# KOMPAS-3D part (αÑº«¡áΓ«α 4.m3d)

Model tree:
1. Эскиз:1
2. Операция выдавливания:36
     Толщина стенки 1 = 2; Толщина стенки 2 = 6; Расстояние 1 = 1; Расстояние 2 = 3
3. Эскиз:38
4. Операция выдавливания:40
     Толщина стенки 1 = 2; Толщина стенки 2 = 6; Расстояние 1 = 5; Расстояние 2 = 3
5. Эскиз:39
6. Операция выдавливания:41
     Толщина стенки 1 = 2; Толщина стенки 2 = 6; Расстояние 1 = 1; Расстояние 2 = 3
7. Эскиз:40
8. Операция выдавливания:42
     Толщина стенки 1 = 2; Толщина стенки 2 = 2.5; Расстояние 1 = 50; Расстояние 2 = 3
9. Эскиз:41
10. Вырезать элемент выдавливания:4
     Толщина стенки 2 = 1.5; Расстояние 1 = 40
11. Эскиз:42
12. Операция выдавливания:43
     Толщина стенки 1 = 2; Толщина стенки 2 = 2.5; Расстояние 1 = 50; Расстояние 2 = 3
13. Эскиз:43
14. Вырезать элемент выдавливания:5
     Толщина стенки 2 = 1.5; Расстояние 1 = 40
15. Эскиз:44
16. Операция выдавливания:44
     Толщина стенки 1 = 2; Толщина стенки 2 = 2.5; Расстояние 1 = 10; Расстояние 2 = 3
17. Эскиз:45
18. Эскиз:46
19. Операция выдавливания:47
     Толщина стенки 1 = 2; Толщина стенки 2 = 6; Расстояние 1 = 1; Расстояние 2 = 3
20. Эскиз:47
21. Операция выдавливания:48
     Толщина стенки 1 = 2; Толщина стенки 2 = 6; Расстояние 1 = 5; Расстояние 2 = 3
22. Эскиз:48
23. Операция выдавливания:49
     Толщина стенки 1 = 2; Толщина стенки 2 = 6; Расстояние 1 = 1; Расстояние 2 = 3
24. Эскиз:49
25. Вырезать элемент выдавливания:6
     Толщина стенки 2 = 1.5; Расстояние 1 = 22
26. Эскиз:50
27. Вырезать элемент выдавливания:7
     Толщина стенки 2 = 1.5; Расстояние 1 = 1
28. Эскиз:51
29. Вырезать элемент выдавливания:8
     Толщина стенки 2 = 1.5; Расстояние 1 = 151
30. Эскиз:52
31. Операция выдавливания:50
     Толщина стенки 1 = 5; Толщина стенки 2 = 6; Расстояние 1 = 1; Расстояние 2 = 0.5
